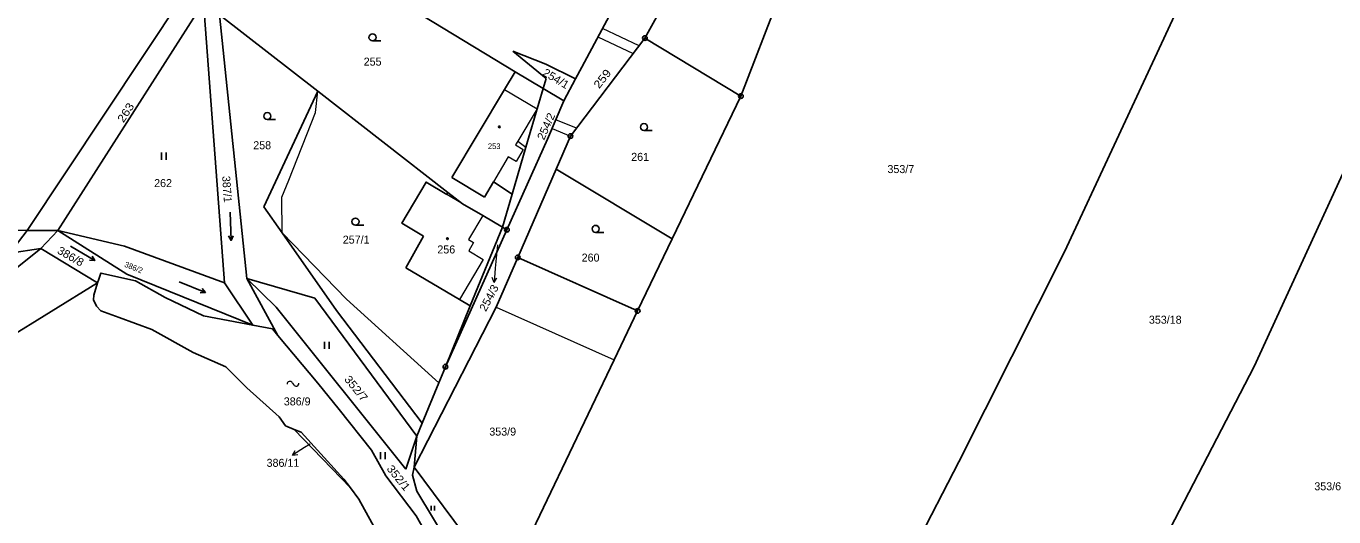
# Model space of a CAD drawing. Extents: x -504006 to -501322, y -1128098 to -1124665.
# Drawn here: x -502830.4 to -502552.5, y -1127108.2 to -1127003.9 of the extents above; entities that cross this region are included whole.
import ezdxf
from ezdxf.enums import TextEntityAlignment as Align

# ---------------------------------------------------------------- set-up
doc = ezdxf.new("R2010")
doc.units = 0
doc.header["$LTSCALE"] = 0.68
for name, color, linetype, lineweight in [('1', 7, 'Continuous', 25), ('13', 7, 'Continuous', 13), ('3', 7, 'Continuous', 25), ('4', 7, 'Continuous', 13), ('5', 7, 'Continuous', 25), ('7', 7, 'Continuous', 13), ('8', 7, 'Continuous', 25)]:
    doc.layers.add(name, color=color, linetype=linetype, lineweight=lineweight)
doc.layers.add('2', color=7, linetype='Continuous')

msp = doc.modelspace()

# ---------------------------------------------------------------- linework, layer by layer
at = {"layer": '1'}
for p, q in [((-502546.27, -1126915.37), (-502588.67, -1127006.49)), ((-502569.42, -1127076.25), (-502506.22, -1126938.15)), ((-502678.51, -1127018.76), (-502663.72, -1126980.38)), ((-502685.21, -1126981.83), (-502698.9, -1127006.42)), ((-502830.12, -1127047.35), (-502794.44, -1126993.56)), ((-502701.6, -1126992.5), (-502712.32, -1127012.6)), ((-502726.47, -1127013.56), (-502752.9, -1126997.52)), ((-502823.66, -1127047.34), (-502792.68, -1126998.83)), ((-502792.68, -1126998.83), (-502788.22, -1127058.48)), ((-502768.42, -1127017.71), (-502789.27, -1127001.48)), ((-502783.5, -1127057.54), (-502789.27, -1127001.48)), ((-502698.9, -1127006.42), (-502714.71, -1127027.26)), ((-502698.9, -1127006.42), (-502678.51, -1127018.76)), ((-502588.67, -1127006.49), (-502609.77, -1127051.84)), ((-502726.95, -1127009.16), (-502719.86, -1127014.97)), ((-502719.92, -1127011.94), (-502726.95, -1127009.16)), ((-502728.73, -1127017.34), (-502726.47, -1127013.56)), ((-502720.5, -1127017.14), (-502726.47, -1127013.56)), ((-502713.64, -1127015.09), (-502719.92, -1127011.94)), ((-502712.32, -1127012.6), (-502713.64, -1127015.09)), ((-502720.5, -1127017.14), (-502724.18, -1127029.62)), ((-502719.86, -1127014.97), (-502720.5, -1127017.14)), ((-502720.5, -1127017.14), (-502716.13, -1127019.76)), ((-502713.64, -1127015.09), (-502716.13, -1127019.76)), ((-502779.88, -1127042.26), (-502768.42, -1127017.71)), ((-502740.77, -1127039.24), (-502768.42, -1127017.71)), ((-502739.91, -1127036.09), (-502728.73, -1127017.34)), ((-502716.13, -1127019.76), (-502719.58, -1127027.92)), ((-502678.51, -1127018.76), (-502693.08, -1127049.1)), ((-502719.58, -1127027.92), (-502728.22, -1127047.17)), ((-502714.71, -1127027.26), (-502717.76, -1127034.29)), ((-502724.18, -1127029.62), (-502727.12, -1127039.6)), ((-502733, -1127040.21), (-502739.91, -1127036.09)), ((-502717.76, -1127034.29), (-502725.92, -1127053.05)), ((-502717.76, -1127034.29), (-502693.08, -1127049.1)), ((-502741, -1127039.66), (-502740.77, -1127039.24)), ((-502737.65, -1127041.67), (-502740.77, -1127039.24)), ((-502731.1, -1127037.01), (-502733, -1127040.21)), ((-502727.12, -1127039.6), (-502731.1, -1127037.01)), ((-502733.36, -1127044.17), (-502737.65, -1127041.67)), ((-502729.19, -1127046.6), (-502727.12, -1127039.6)), ((-502775.94, -1127047.82), (-502779.88, -1127042.26)), ((-502729.19, -1127046.6), (-502733.36, -1127044.17)), ((-502830.12, -1127047.35), (-502847.96, -1127046.92)), ((-502833.8, -1127052.17), (-502830.12, -1127047.35)), ((-502823.66, -1127047.34), (-502830.12, -1127047.35)), ((-502809.47, -1127050.66), (-502823.66, -1127047.34)), ((-502809, -1127056.61), (-502823.66, -1127047.34)), ((-502741.29, -1127076.28), (-502728.22, -1127047.17)), ((-502736.01, -1127063.32), (-502729.19, -1127046.6)), ((-502729.19, -1127046.6), (-502728.22, -1127047.17)), ((-502764.45, -1127064.33), (-502775.94, -1127047.82)), ((-502749.71, -1127055.28), (-502745.93, -1127048.5)), ((-502693.08, -1127049.1), (-502700.44, -1127064.42)), ((-502866.23, -1127082.3), (-502827.25, -1127051.17)), ((-502833.8, -1127052.17), (-502827.25, -1127051.17)), ((-502827.25, -1127051.17), (-502815.24, -1127058.45)), ((-502788.22, -1127058.48), (-502809.47, -1127050.66)), ((-502725.92, -1127053.05), (-502730.51, -1127063.6)), ((-502700.44, -1127064.42), (-502725.92, -1127053.05)), ((-502609.77, -1127051.84), (-502632.21, -1127096.54)), ((-502815.24, -1127058.45), (-502834.86, -1127070.61)), ((-502782.18, -1127067.46), (-502809, -1127056.61)), ((-502788.22, -1127058.48), (-502782.18, -1127067.46)), ((-502777.26, -1127063.65), (-502783.5, -1127057.54)), ((-502769.05, -1127061.68), (-502783.5, -1127057.54)), ((-502776.88, -1127069.63), (-502783.5, -1127057.54)), ((-502749.67, -1127098.07), (-502777.26, -1127063.65)), ((-502747.34, -1127091.09), (-502769.05, -1127061.68)), ((-502746.21, -1127088.31), (-502764.45, -1127064.33)), ((-502730.51, -1127063.6), (-502747.91, -1127097.64)), ((-502741.29, -1127076.28), (-502736.01, -1127063.32)), ((-502705.41, -1127074.79), (-502700.44, -1127064.42)), ((-502725.15, -1127115.98), (-502705.41, -1127074.79)), ((-502741.29, -1127076.28), (-502742.69, -1127079.69)), ((-502634.94, -1127202.57), (-502569.42, -1127076.25)), ((-502742.69, -1127079.69), (-502746.21, -1127088.31)), ((-502746.21, -1127088.31), (-502747.34, -1127091.09)), ((-502773.4, -1127089.61), (-502761.47, -1127102.05)), ((-502747.34, -1127091.09), (-502749.67, -1127098.07)), ((-502747.91, -1127097.64), (-502747.34, -1127091.09)), ((-502748.29, -1127099.37), (-502747.91, -1127097.64)), ((-502733.39, -1127117.12), (-502747.91, -1127097.64)), ((-502632.21, -1127096.54), (-502652.16, -1127135.22)), ((-502747.36, -1127102.72), (-502748.29, -1127099.37)), ((-502738.29, -1127117.8), (-502747.36, -1127102.72))]:
    msp.add_line(p, q, dxfattribs=at)
for points in [[(-502741, -1127039.66), (-502745.39, -1127037.02), (-502750.57, -1127045.74), (-502745.93, -1127048.5)], [(-502736.01, -1127063.32), (-502738.31, -1127061.97), (-502749.71, -1127055.28)], [(-502773.4, -1127089.61), (-502775.23, -1127088.86), (-502776.63, -1127086.93), (-502783.46, -1127080.75), (-502787.97, -1127076.28), (-502794.89, -1127073.25), (-502803.63, -1127068.37), (-502810.61, -1127065.84), (-502814.51, -1127064.43), (-502815.41, -1127063.4), (-502816.08, -1127062.09), (-502815.96, -1127061.06), (-502815.24, -1127058.45)], [(-502815.24, -1127058.45), (-502814.89, -1127057.69), (-502814.47, -1127056.37), (-502807.1, -1127058.03), (-502800.83, -1127061.57), (-502792.71, -1127065.47), (-502782.18, -1127067.46)], [(-502782.18, -1127067.46), (-502778.04, -1127068.24), (-502776.88, -1127069.63)], [(-502776.88, -1127069.63), (-502768.42, -1127079.76), (-502763.87, -1127085.36), (-502756.97, -1127094.05), (-502753.92, -1127099.5), (-502747.51, -1127108.03), (-502744.64, -1127113.03), (-502744.68, -1127115.26)], [(-502761.47, -1127102.05), (-502762.86, -1127100.23), (-502771.92, -1127090.22), (-502773.4, -1127089.61)], [(-502763.02, -1127180.62), (-502766.12, -1127176.67), (-502765.66, -1127174.95), (-502764.31, -1127172.47), (-502760.11, -1127167), (-502753.81, -1127154.75), (-502751.04, -1127148.8), (-502750.63, -1127144.04), (-502751.02, -1127141.83), (-502749.92, -1127132.47), (-502753.21, -1127121.9), (-502755.1, -1127120.04), (-502754.78, -1127115.81), (-502755.39, -1127112.35), (-502759.66, -1127104.43), (-502761.47, -1127102.05)]]:
    msp.add_lwpolyline(points, dxfattribs=at)
at = {"layer": '13'}
for points in [[(-502708.88, -1127006.15), (-502701.38, -1127009.69), (-502700.14, -1127008.06), (-502707.94, -1127004.39)], [(-502717.82, -1127023.76), (-502718.6, -1127025.61), (-502714.71, -1127027.26), (-502713.45, -1127025.6)]]:
    msp.add_lwpolyline(points, close=True, dxfattribs=at)
at = {"layer": '3'}
for p, q in [((-502756.773, -1127007.01), (-502755.023, -1127007.01)), ((-502779.123, -1127023.74), (-502777.373, -1127023.74)), ((-502699.093, -1127026.08), (-502697.343, -1127026.08)), ((-502801.591, -1127032.27), (-502801.591, -1127030.77)), ((-502800.59, -1127032.27), (-502800.59, -1127030.77)), ((-502760.393, -1127046.19), (-502758.643, -1127046.19)), ((-502709.373, -1127047.73), (-502707.623, -1127047.73)), ((-502786.813, -1127049.436), (-502787.348, -1127048.477)), ((-502815.778, -1127053.711), (-502816.874, -1127053.638)), ((-502792.276, -1127060.498), (-502793.37, -1127060.597)), ((-502766.981, -1127072.48), (-502766.981, -1127070.98)), ((-502765.98, -1127072.48), (-502765.98, -1127070.98)), ((-502755.071, -1127095.97), (-502755.071, -1127094.47)), ((-502754.07, -1127095.97), (-502754.07, -1127094.47)), ((-502744.298, -1127106.89), (-502744.298, -1127105.84)), ((-502743.597, -1127106.89), (-502743.597, -1127105.84))]:
    msp.add_line(p, q, dxfattribs=at)
for points in [[(-502787.023, -1127043.439), (-502786.813, -1127049.436), (-502786.346, -1127048.442)], [(-502820.921, -1127050.621), (-502815.778, -1127053.711), (-502816.358, -1127052.778)], [(-502797.839, -1127058.251), (-502792.276, -1127060.498), (-502792.994, -1127059.667)]]:
    msp.add_lwpolyline(points, dxfattribs=at)
for centre in [(-502756.7729, -1127006.2598), (-502779.1229, -1127022.9898), (-502699.0929, -1127025.3298), (-502760.3929, -1127045.4398), (-502709.3729, -1127046.9798)]:
    msp.add_circle(centre, 0.75, dxfattribs=at)
at = {"layer": '4'}
for p, q in [((-502768.88, -1127022.24), (-502768.42, -1127017.71)), ((-502728.73, -1127017.34), (-502721.82, -1127021.46)), ((-502774.54, -1127036.62), (-502768.88, -1127022.24)), ((-502721.82, -1127021.46), (-502725.91, -1127028.32)), ((-502725.91, -1127028.32), (-502726.38, -1127029.11)), ((-502726.38, -1127029.11), (-502724.73, -1127030.1)), ((-502724.73, -1127030.1), (-502726.27, -1127032.67)), ((-502725.91, -1127028.32), (-502724.18, -1127029.62)), ((-502727.92, -1127031.69), (-502731.1, -1127037.01)), ((-502726.27, -1127032.67), (-502727.92, -1127031.69)), ((-502776.01, -1127040.21), (-502774.54, -1127036.62)), ((-502775.94, -1127047.82), (-502776.01, -1127040.21)), ((-502737.65, -1127041.67), (-502741, -1127039.66)), ((-502823.66, -1127047.34), (-502827.25, -1127051.17)), ((-502762.3, -1127061.96), (-502775.94, -1127047.82)), ((-502733.29, -1127053.49), (-502738.31, -1127061.97)), ((-502743.4, -1127079.05), (-502762.3, -1127061.96)), ((-502730.51, -1127063.6), (-502705.41, -1127074.79)), ((-502742.69, -1127079.69), (-502743.4, -1127079.05))]:
    msp.add_line(p, q, dxfattribs=at)
msp.add_lwpolyline([(-502733.36, -1127044.17), (-502736.35, -1127049.23), (-502735.3, -1127049.88), (-502736.33, -1127051.67), (-502733.29, -1127053.49)], dxfattribs=at)
at = {"layer": '5', "lineweight": 13}
msp.add_line((-502773.82, -1127079.72), (-502773.52, -1127080.12), dxfattribs=at)
at = {"layer": '5'}
for centre in [(-502729.8368, -1127025.2892), (-502740.8468, -1127049.0692)]:
    msp.add_circle(centre, 0.175, dxfattribs=at)
at = {"layer": '5', "lineweight": 13}
for centre, start, end in [((-502774.3325, -1127080.0073), 29.29136, 181.21888), ((-502773.0075, -1127079.8323), 209.29136, 1.21887)]:
    msp.add_arc(centre, 0.5876, start, end, dxfattribs=at)
at = {"layer": '7'}
for p, q in [((-502730.942, -1127058.35), (-502730.355, -1127057.396)), ((-502773.765, -1127095.08), (-502772.65, -1127094.974))]:
    msp.add_line(p, q, dxfattribs=at)
for points in [[(-502730.24, -1127050.36), (-502730.68, -1127055.36), (-502730.942, -1127058.35), (-502731.353, -1127057.308)], [(-502770, -1127092.74), (-502771.22, -1127093.49), (-502773.765, -1127095.08), (-502773.181, -1127094.125)]]:
    msp.add_lwpolyline(points, dxfattribs=at)
at = {"layer": '8'}
for centre, radius in [((-502698.9, -1127006.4199), 0.5), ((-502698.9, -1127006.4199), 0.0303), ((-502678.51, -1127018.7599), 0.5), ((-502678.51, -1127018.7599), 0.0303), ((-502714.71, -1127027.2599), 0.5), ((-502714.71, -1127027.2599), 0.0303), ((-502728.22, -1127047.1699), 0.5), ((-502728.22, -1127047.1699), 0.0303), ((-502725.92, -1127053.0499), 0.5), ((-502725.92, -1127053.0499), 0.0303), ((-502700.44, -1127064.4199), 0.5), ((-502700.44, -1127064.4199), 0.0303), ((-502741.29, -1127076.2799), 0.5), ((-502741.29, -1127076.2799), 0.0303)]:
    msp.add_circle(centre, radius, dxfattribs=at)

# ---------------------------------------------------------------- texts
at = {"layer": '2'}
for s, height, p in [('255', 1.7, (-502756.749, -1127012.265)), ('258', 1.7, (-502780.219, -1127030.045)), ('253', 1.2, (-502730.919, -1127030.01)), ('261', 1.7, (-502699.909, -1127032.515)), ('353/7', 1.7, (-502644.52, -1127035.115)), ('262', 1.7, (-502801.279, -1127038.095)), ('257/1', 1.7, (-502760.25, -1127050.115)), ('256', 1.7, (-502741.099, -1127052.205)), ('260', 1.7, (-502710.439, -1127053.935)), ('353/18', 1.7, (-502588.34, -1127067.145)), ('386/9', 1.7, (-502772.78, -1127084.515)), ('353/9', 1.7, (-502729.11, -1127090.935)), ('386/11', 1.7, (-502775.8, -1127097.575)), ('353/6', 1.7, (-502553.82, -1127102.565))]:
    msp.add_text(s, height=height, dxfattribs=at).set_placement(p, align=Align.CENTER)
at = {"layer": '2', "width": 1.05}
for s, rotation, p in [('254/1', 329, (-502720.788, -1127014.214)), ('254/2', 66, (-502720.331, -1127028.242)), ('386/8', 330, (-502823.912, -1127052.068))]:
    msp.add_text(s, height=1.7, rotation=rotation, dxfattribs=at).set_placement(p)
at = {"layer": '2'}
for s, rotation, width, p in [('259', 52, 1.15, (-502707.2765, -1127015.5843)), ('263', 57, 1.15, (-502808.5001, -1127022.7054)), ('254/3', 62, 1.05, (-502731.2864, -1127062.0556)), ('352/7', 309, 1.1, (-502760.9195, -1127081.4396)), ('352/1', 309, 1.1, (-502751.8995, -1127100.4596))]:
    msp.add_text(s, height=1.7, rotation=rotation, dxfattribs=dict(at, width=width)).set_placement(p, align=Align.CENTER)
msp.add_text('387/1', height=1.7, rotation=274, dxfattribs=at).set_placement((-502788.723, -1127035.779))
msp.add_text('386/2', height=1.2, rotation=338, dxfattribs=at).set_placement((-502807.7473, -1127055.7342), align=Align.CENTER)

doc.saveas('drawing.dxf')
